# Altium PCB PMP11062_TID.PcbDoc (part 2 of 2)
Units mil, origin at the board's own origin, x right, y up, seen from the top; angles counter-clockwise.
Board outline 8000 x 4750 mil, 2 copper layers (Top Layer, Bottom Layer), stack 62 mil thick; 95 components, 41 nets, 236 pads, 20 vias.
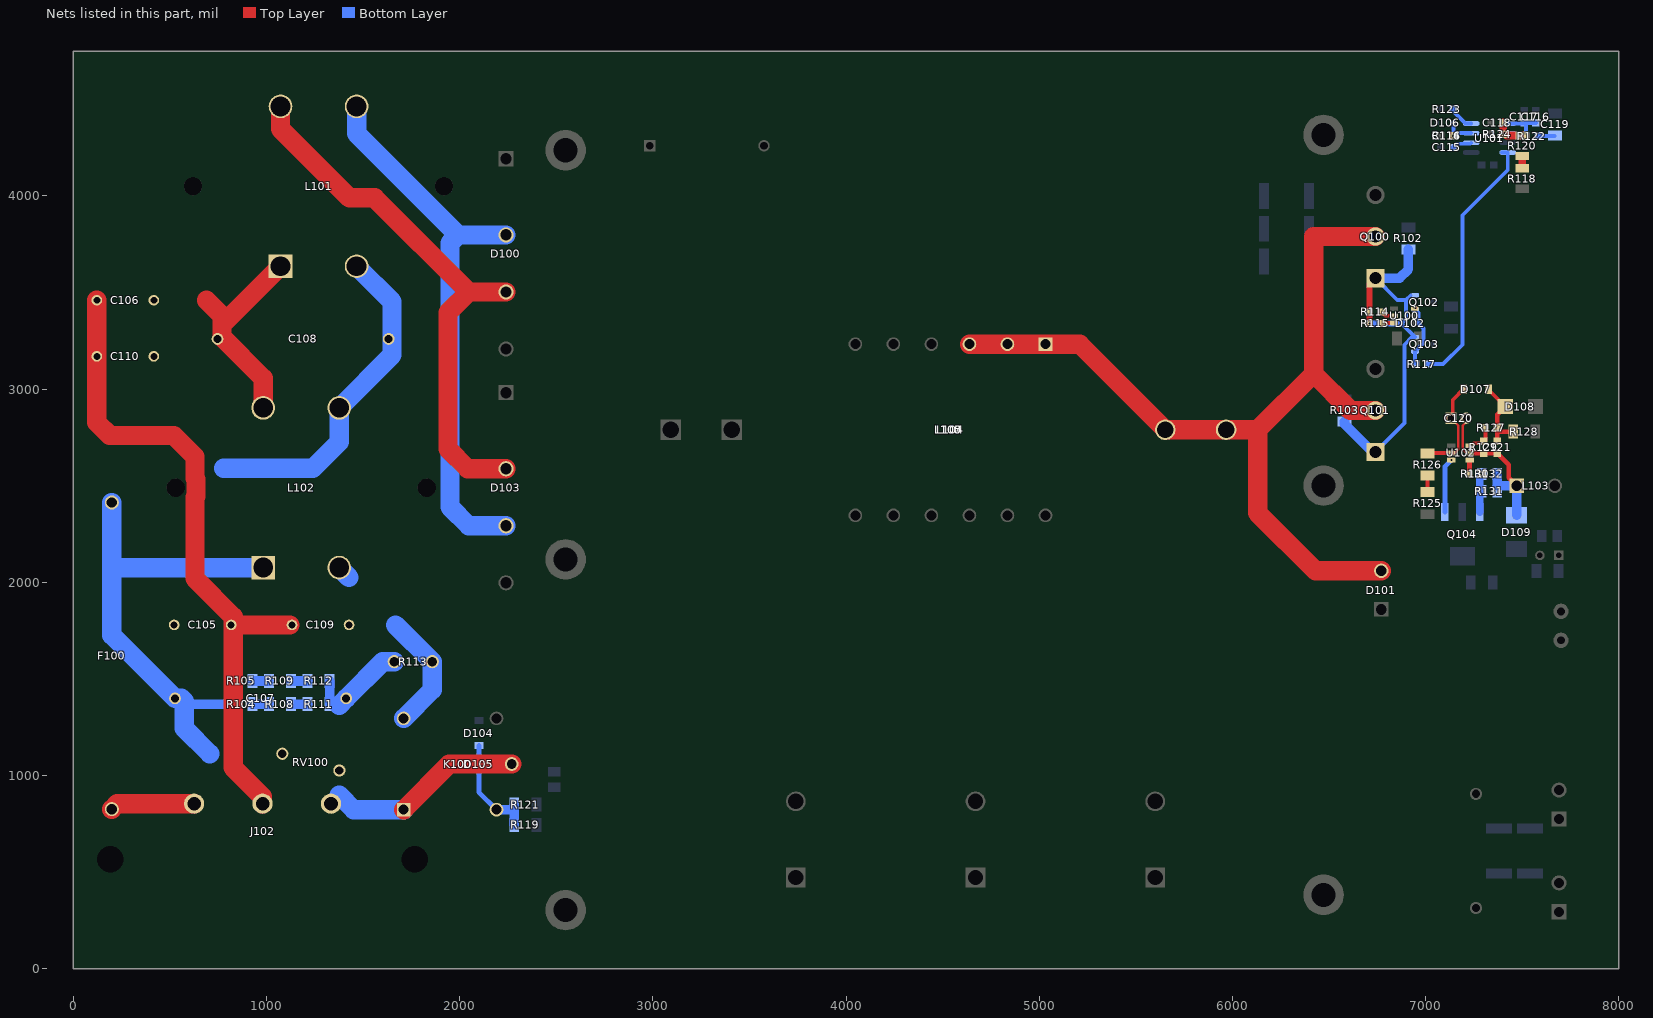
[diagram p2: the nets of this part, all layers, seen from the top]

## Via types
v1: diameter 28, hole 10, Top Layer to Bottom Layer, 20 vias

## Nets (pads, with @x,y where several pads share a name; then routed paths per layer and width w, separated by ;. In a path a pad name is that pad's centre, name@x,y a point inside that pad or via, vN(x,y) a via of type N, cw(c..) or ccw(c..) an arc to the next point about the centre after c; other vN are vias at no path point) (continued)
NetC105_1: C105.1 C107.1 F100.2 L102.1 R104.2 R105.2 RV100.2 | length 2642.2
  Bottom Layer w50: 590,1370 R104.2@812.91,1370 R105.2@812.91,1490
  Bottom Layer w100: F100.2@200,2413.7 200,1727.09 C107.1@527.09,1400 560,1400 575.51,1384.49 575.51,1244.49 706.69,1113.31 ; 213.39,2076.61 L102.1@983.15,2076.61
NetC106_1: C106.1 C108.1 L101.1 L102.4 | length 1106.8
  Top Layer w100: 690,3460 770,3380 770,3333.46 ; L102.4@983.15,2903.39 983.15,3056.85 770,3270 770,3333.46 ; L101.1@1073.15,3636.61 770,3333.46
NetC107_2: C107.2 J102.2 K100.1 K100.3 R111.1 R112.1 R113.2 RV100.1 | length 1517.9
  Top Layer w100: K100.1@1710.47,823.78 1946.69,1060 K100.3@2269.53,1060
  Bottom Layer w50: R111.1@1327.09,1370 R112.1@1327.09,1490
  Bottom Layer w100: 1377.64,898.31 1452.17,823.78 K100.1@1710.47,823.78 ; 1377.64,1364.72 C107.2@1412.91,1400 1602.91,1590 R113.2@1661.57,1590
NetC108_2: C108.2 C110.2 L101.2 L102.3 | length 1752.3
  Bottom Layer w100: 780,2590 1240,2590 1376.85,2726.85 L102.3@1376.85,2903.39 1650,3176.54 1650,3453.46 L101.2@1466.85,3636.61
NetC109_2: C109.2 K100.2 L102.2 R113.1 | length 695.6
  Bottom Layer w100: L102.2@1376.85,2076.61 1427.64,2025.83 ; 1668.43,1780 R113.1@1858.43,1590 1858.43,1444.17 K100.2@1710.47,1296.22
NetC114_1: C114.1 D106.1 R116.1 U101.3 | length 166.4
  Bottom Layer w20: v1(7141.5,4311.46) 7151.46,4311.46 7165,4325 U101.3@7235.51,4325 ; C114.1@7143.31,4313.27 D106.1@7143.31,4380
NetC115_1: C115.1 U101.2 | length 103.8
  Bottom Layer w20: C115.1@7141.5,4251.46 7160.04,4270 7230.51,4270 U101.2@7235.51,4275
NetC116_1: C116.1 C117.1 R122.2 U101.5 | length 219
  Bottom Layer w20: U101.5@7424.49,4375 7506.5,4375 C117.1@7510,4378.5 ; R122.2@7518.5,4310 7518.5,4370 C117.1@7510,4378.5 ; C116.1@7570,4378.5 C117.1@7510,4378.5
NetC118_1: C118.1 R120.1 R124.2 U101.6 | length 155.4
  Top Layer w39.37: C118.1@7401.5,4380 7401.5,4330.2 v1(7406.69,4325) 7418.54,4313.15 R120.1@7500,4313.15
NetC119_1: C119.1 R122.1 | length 85.6
  Bottom Layer w20: R122.1@7581.5,4310 C119.1@7667.09,4310
NetC120_1: C120.1 D107.1 R126.2 U102.2 | length 503.9
  Top Layer w12: C120.1@7130.63,2850 7168.28,2812.35 7168.28,2688.28 7150,2670 U102.2@7132.76,2670
  Top Layer w20: R126.2@7012.91,2670 U102.2@7132.76,2670 ; C120.1@7140,2859.37 7140,2944.47 D107.1@7195.53,3000
NetC120_2: C120.2 C121.2 D109.1 L103.1 R129.1 R131.2 R132.2 U102.5 | length 852.9
  Top Layer w12: C120.2@7209.37,2850 7209.37,2829.37 7191.72,2811.72 7191.72,2688.28 7210,2670 U102.5@7227.24,2670
  Top Layer w25: U102.5@7227.24,2670 R129.1@7301.57,2670 ; R129.1@7300,2668.5 C121.2@7370,2668.5 7430,2608.5 7430,2541.57 L103.1@7471.57,2500
  Bottom Layer w50: R131.2@7370,2500 R132.2@7370,2561.46 ; 7398.54,2500 L103.1@7471.57,2500 D109.1@7471.57,2348.58
NetC121_1: C121.1 D107.2 D108.1 R127.2 R128.2 | length 404.5
  Top Layer w20: D107.2@7324.47,3000 7324.47,2996.79 D108.1@7411.26,2910
  Top Layer w25: C121.1@7370,2731.5 7370,2780 ; D108.1@7411.26,2910 7370,2868.74 7370,2780 ; R128.2@7452.91,2780 7370,2780
NetD100_2: D100.2 D103.3 L101.3 | length 2886.5
  Bottom Layer w100: L101.3@1466.85,4463.39 1466.85,4323.15 1991.57,3798.43 ; D103.3@2240,2293.15 2046.85,2293.15 1950,2390 1950,3756.85 1991.57,3798.43 ; D100.2@2240,3798.43 1991.57,3798.43
NetD100_3: D100.3 D103.2 L101.4 | length 2832.3
  Top Layer w100: L101.4@1073.15,4463.39 1073.15,4346.85 1430,3990 1560,3990 2046.85,3503.15 ; D103.2@2240,2588.43 2041.57,2588.43 1940,2690 1940,3396.3 2046.85,3503.15 ; D100.3@2240,3503.15 2046.85,3503.15
NetD101_2: D101.2 L100.2 L104.1 L104.2 L104.3 L105.2 Q100.2 Q101.2 | length 4708.1
  Top Layer w100: L104.3@4638.43,3232.91 L104.2@4835.28,3232.91 L104.1@5032.13,3232.91 5209.13,3232.91 L100.2@5652.05,2790 6130,2790 ; Q101.2@6740,2890 6610,2890 6420,3080 ; Q100.2@6740,3790 6420,3790 6420,3080 ; D101.2@6770,2060 6430,2060 6130,2360 6130,2790 ; 6130,2790 6420,3080
NetD102_1: D102.1 Q100.1 Q101.1 Q102.2 Q103.2 R102.2 R103.2 R114.1 R115.2 | length 2038
  Top Layer w29.53: v1(6708.5,3340) R114.1@6708.5,3400 Q100.1@6708.5,3543.5
  Bottom Layer w20: Q101.1@6740,2675 6890,2825 6890,3230 6929.57,3269.57 Q103.2@6944.41,3269.57 6875.39,3338.59 D102.1@6875.39,3340.16 6898.7,3363.46 6898.7,3462.52 ; Q100.1@6740,3575 6852.48,3462.52 6898.7,3462.52 ; 6922.64,3486.46 6898.7,3462.52
  Bottom Layer w29.53: v1(6708.5,3340) D102.1@6875.24,3340
  Bottom Layer w50: R103.2@6580,2832.91 6580,2820 Q101.1@6725,2675 ; Q100.1@6740,3575 6865,3575 6910,3620 R102.2@6910,3722.91
NetD102_2: D102.2 Q102.1 Q103.1 R117.1 U100.6 | length 314.1
  Bottom Layer w20: R117.1@6944.41,3134.09 Q103.1@6944.41,3194.77 6988.7,3239.06 6988.7,3313.46 D102.2@6962.01,3340.16 6962.01,3394.53 Q102.1@6944.88,3411.65
  other v1: 6946.46,3419.51
NetD104_2: D104.2 D105.2 | length 52.2
  Bottom Layer w25: D105.2@2100,1103.31 D104.2@2100,1155.53
NetD105_1: D105.1 K100.4 R119.1 R121.1 | length 442.1
  Bottom Layer w25: D105.1@2100,1016.69 2100,914.57 K100.4@2190.79,823.78 ; R121.1@2262.91,830 R121.1@2282.91,850
  Bottom Layer w50: K100.4@2190.79,823.78 R121.1@2269.13,823.78 ; R119.1@2282.91,745.04 R121.1@2282.91,850
NetF100_1: F100.1 J102.1 | length 437.6
  Top Layer w100: F100.1@200,826.3 228.7,855 J102.1@625.67,855
NetQ104_1: Q104.1 U102.3 | length 282.2
  Bottom Layer w25: Q104.1@7099.45,2364.17 7099.45,2599.29 v1(7132.76,2632.6)
NetQ104_3: Q104.3 R130.1 R131.1 R132.1 | length 187.8
  Bottom Layer w39.37: Q104.3@7280.55,2364.17 R132.1@7280.55,2552.01
  other v1: 7287.5,2561.46
NetR104_1: R104.1 R108.2 | length 85.8
  Bottom Layer w50: R104.1@927.09,1370 R108.2@1012.91,1370
NetR105_1: R105.1 R109.2 | length 85.8
  Bottom Layer w50: R105.1@927.09,1490 R109.2@1012.91,1490
NetR108_1: R108.1 R111.2 | length 85.8
  Bottom Layer w50: R108.1@1127.09,1370 R111.2@1212.91,1370
NetR109_1: R109.1 R112.2 | length 85.8
  Bottom Layer w50: R109.1@1127.09,1490 R112.2@1212.91,1490
NetR114_2: R114.2 U100.2 | length 72.7
  Top Layer w20: R114.2@6771.5,3400 6791.5,3380 U100.2@6835.87,3380
NetR115_1: R115.1 U100.3 | length 61.8
  Top Layer w20: R115.1@6774.09,3342.6 U100.3@6835.87,3342.6
NetR117_2: R117.2 U101.8 | length 1341.5
  Bottom Layer w20: R117.2@7011.5,3130 7090,3130 7190,3230 7190,3900 7424.49,4134.49 U101.8@7424.49,4225 U101.8@7395,4225
NetR118_1: R118.1 R120.2 | length 63.7
  Top Layer w39.37: R118.1@7500,4143.15 R120.2@7500,4206.85
NetR123_2: R123.2 U101.4 | length 130.9
  Bottom Layer w20: R123.2@7141.5,4450 7141.5,4440 7206.5,4375 U101.4@7235.51,4375
NetR125_2: R125.2 R126.1 | length 85.8
  Top Layer w20: R125.2@7010,2467.09 R126.1@7010,2552.91
NetR127_1: R127.1 R129.2 U102.6 | length 154.8
  Top Layer w20: U102.6@7227.24,2707.4 7237.4,2707.4 7250,2720 7288.5,2720 R129.2@7300,2731.5 7308.5,2740 R127.1@7308.5,2800
NetR130_2: R130.2 U102.4 | length 68.4
  Top Layer w25: R130.2@7227.24,2564.2 U102.4@7227.24,2632.6
PE: C105.2 C106.2 C109.1 C110.1 J102.3 | length 3452.8
  Top Layer w100: C106.2@122.36,3460 C110.1@122.36,3170 122.36,2827.64 190,2760 520,2760 630,2650 630,2539.05 635.51,2533.54 635.51,2446.46 630,2440.95 630,2020 827.64,1822.36 C105.2@827.64,1780 ; J102.3@980,855 980,890 827.64,1042.36 C105.2@827.64,1780 ; C109.1@1122.36,1780 C105.2@827.64,1780
pads on no net: J102.MH1 J102.MH2 L101.MH1 L101.MH2 L102.MH1 L102.MH2 L104.7 L104.8 L104.9 L104.10 L104.11 L104.12 U102.1

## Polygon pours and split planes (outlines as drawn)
NetC103_2 on Top Layer "C103_2" (solid, remove dead copper, pour order 54): 2850,2000 2850,1900 2850,440 2850,200 2850,30 2830,10 2810,10 2210,10 2190,30 2190,450 2190,1300 2250,1360 2370,1360 2380,1360 2400,1380 2400,1400 2400,1740 2180,1960 2180,2030 2200,2050 2280,2050 2430,2200 2430,2500 2430,4660 2450,4680 2480,4680 3600,4680 3620,4660 3620,4630 3620,4490 3620,3140 3040,2560 2870,2390 2850,2390
GND on Top Layer "GND" (solid, remove dead copper, pour order 56): 2210,10 2190,30 2190,80 2190,410 2190,1300 2240,1350 2250,1360 3690,1360 5360,1360 5610,1360 5930,1680 5930,2260 5930,4660 5950,4680 5990,4680 7970,4680 7990,4660 7990,4650 7990,30 7970,10
B+ on Top Layer "B+" (solid, remove dead copper, pour order 53): 6810,1910 6830,1890 6830,1730 6830,1610 7340,1100 7640,1100 7720,1100 7740,1080 7740,1060 7740,690 7720,670 7710,670 6460,670 6160,370 5910,120 3720,120 3650,120 3630,140 3630,170 3630,560 3650,580 3660,580 5640,580 6350,1290 6350,1780 6350,1890 6370,1910
NetD101_2 on Top Layer "D101_2" (solid, remove dead copper, pour order 51): 4580,3160 4600,3140 5210,3140 5300,3050 6350,2000 6770,2000 6810,2000 6830,2020 6830,2050 6830,2130 6810,2150 6790,2150 6630,2150 6340,2440 6340,2450 6340,2560 6590,2810 6620,2840 6680,2840 6780,2840 6800,2860 6800,2870 6800,2930 6780,2950 6760,2950 6690,2950 6610,3030 6610,3060 6610,3670 6680,3740 6770,3740 6780,3740 6800,3760 6800,3820 6780,3840 6431.57,3840 6350,3840 6330,3820 6330,3790 6330,3510 6220,3400 6090,3400 4600,3400 4580,3380
NetC103_1 on Top Layer "C103_1" (solid, remove dead copper, pour order 50): 2210,4250 2190,4230 2190,4210 2190,4160 2200,4150 2210,4140 2218.35,4140 2220,4140 2240,4120 2450,3910 2450,3740 2450,3150 2340,3040 2300,3040 2210,3040 2190,3020 2190,3010 2190,2930 2270,2850 2310,2850 2470,2850 2650,2670 3230,2670 4010,2670 4500,3160 4500,3190 4500,3290 4480,3310 4420,3310 4410,3320 4290,3440 3920,3810 3550,3810 3130,4230 3130,4290 3110,4310 3050,4310 2270,4310
NetD100_3 on Top Layer "D100_3" (solid, remove dead copper, pour order 48): 2270,2540 2290,2560 2290,2620 2290,2650 2270,2670 2250,2670 2200,2670 2000,2870 2000,3200 2000,3310 2140,3450 2270,3450 2290,3470 2290,3540 2270,3560 2218.35,3560 2160,3560 1990,3730 1990,3770 1990,4000 1800,4190 1430,4190 1340,4190 1160,4370 1160,4410 1160,4520 1140,4540 1110,4540 970,4540 950,4520 950,4480 950,4200 1270,3880 1520,3880 1580,3880 1690,3770 1730,3730 1730,3640 1730,3500 1830,3400 1830,3140 1730,3040 1730,2600 1790,2540
NetF100_1 on Top Layer "F100_1" (solid, remove dead copper, pour order 40): 50,940 30,920 30,850 30,720 50,700 100,700 660,700 680,720 680,800 680,920 660,940
NetC107_2 on Top Layer "C107_2" (solid, remove dead copper, pour order 43): 1710,1620 1690,1640 1670,1640 1550,1640 1400,1640 1310,1550 1310,1510 1310,1330 1340,1300 1340,1210 1340,940 1290,890 1280,880 1280,860 1280,720 1300,700 1330,700 1740,700 1760,720 1760,760 1760,1150 1640,1270 1640,1290 1640,1410 1710,1480
NetC106_1 on Top Layer "C106_1" (solid, remove dead copper, pour order 47): 390,3450 390,3440 410,3420 430,3420 550,3420 730,3240 730,3150 730,3060 930,2860 950,2840 1020,2840 1060,2840 1080,2860 1090,2870 1090,3060 1090,3160 1150,3220 1150,3560 1150,3690 1130,3710 1020,3710 580,3710 390,3520
GND on Bottom Layer "GND" (solid, remove dead copper, pour order 55): 2210,10 2190,30 2190,80 2190,410 2190,1300 2240,1350 2250,1360 3690,1360 5360,1360 5610,1360 5930,1680 5930,2260 5930,4660 5950,4680 5990,4680 7970,4680 7990,4660 7990,4650 7990,30 7970,10
NetC103_2 on Bottom Layer "C103_2" (solid, remove dead copper, pour order 52): 2200,2050 2180,2030 2180,2010 2180,1960 2200,1940 2240,1940 2830,1940 2850,1960 2850,1980 2850,3030 3350,3530 3530,3530 6210,3530 6230,3550 6230,3570 6230,4040 5590,4680 5420,4680 2450,4680 2430,4660 2430,4630 2430,4500 2430,3920 2430,3440 2260,3270 2250,3260 2220,3260 2210,3260 2190,3240 2190,3170 2200,3160 2218.35,3160 2317.52,3160 2430,3047.52 2430,2200 2280,2050
NetD100_2 on Bottom Layer "D100_2" (solid, remove dead copper, pour order 49): 1390,4520 1410,4540 1490,4540 1530,4540 1850,4220 2170,3900 2230,3900 2270,3900 2290,3880 2290,3850 2290,3770 2270,3750 2218.35,3750 2218.35,3748.35 2210,3740 2050,3580 2050,3480 2050,3370 2050,3050 2050,2500 2190,2360 2280,2360 2300,2340 2300,2310 2300,2260 2280,2240 2260,2240 1950,2240 1730,2460 1730,3400 1730,3580 1630,3680 1390,3920 1390,4270
NetF100_1 on Bottom Layer "F100_1" (solid, remove dead copper, pour order 39): 50,940 30,920 30,850 30,720 50,700 100,700 660,700 680,720 680,800 680,920 660,940
NetC105_1 on Bottom Layer "C105_1" (solid, remove dead copper, pour order 41): 1110,1060 1130,1080 1130,1110 1130,1140 1100,1170 1070,1170 960,1170 830,1300 827.64,1302.36 827.64,1310 827.64,1382.36 550,1660 550,1710 550,1930 640,2020 750,2020 1030,2020 1030,2130 1030,2150 1000,2180 860,2180 580,2180 290,2470 170,2470 120,2470 100,2450 100,2430 100,1080 120,1060
NetC107_2 on Bottom Layer "C107_2" (solid, remove dead copper, pour order 42): 1710,1620 1690,1640 1670,1640 1550,1640 1400,1640 1310,1550 1310,1510 1310,1330 1340,1300 1340,1210 1340,940 1290,890 1280,880 1280,860 1280,720 1300,700 1330,700 1740,700 1760,720 1760,760 1760,1150 1640,1270 1640,1290 1640,1410 1710,1480
NetC109_2 on Bottom Layer "C109_2" (solid, remove dead copper, pour order 44): 1310,2160 1330,2180 1370,2180 1550,2180 1677,2180 2037,1820 2037,1670 2037,1547 1730,1240 1700,1240 1690,1240 1660,1270 1660,1300 1660,1400 1730,1470 1730,1600 1730,1630 1700,1660 1420,1660 1400,1680 1400,1700 1400,1960 1310,2050
NetC108_2 on Bottom Layer "C108_2" (solid, remove dead copper, pour order 45): 410,3200 400,3200 390,3190 390,3180 390,3150 390,3040 390,2680 520,2550 670,2400 790,2400 1530,2400 1700,2570 1700,2700 1700,3560 1550,3710 1440,3710 1410,3710 1390,3690 1390,3670 1390,3160 1310,3080 1310,3000 1310,2820 1140,2650 850,2650 580,2920 510,2990 510,3140 510,3180 490,3200
NetC106_1 on Bottom Layer "C106_1" (solid, remove dead copper, pour order 46): 390,3450 390,3440 410,3420 430,3420 550,3420 730,3240 730,3150 730,3060 930,2860 950,2840 1020,2840 1060,2840 1080,2860 1090,2870 1090,3060 1090,3160 1150,3220 1150,3560 1150,3690 1130,3710 1020,3710 580,3710 390,3520

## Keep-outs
Keep-Out Layer:
  text ".Layer_Name" at 577,-858.49 h60

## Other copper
Top Layer:
  text ".Layer_Name" at 577,-858.49 h60
Bottom Layer:
  text ".Layer_Name" at 577,-858.49 h60

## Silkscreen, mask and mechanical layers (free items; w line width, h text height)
Top Overlay:
  lines w7.01: 0,3543.31 0,0 6692.91,0
  lines w10: 6740,3440 6760,3460 6870,3460 6890,3480 6900,3480 ; 7230,2310 7230,2510 ; 7030,1960 7030,2200 7140,2310 7300,2310 7310,2300 7310,1990 7250,1930 7060,1930 7030,1960
  text ".PRJ_Number" at 5480,50 h60
  text ".PCB_Rev" at 6080,50 h60
  text ".Layer_Name" at 577,-858.49 h60
Bottom Overlay:
  text ".Layer_Name" at 577,-858.49 h60
Top Paste:
  text ".Layer_Name" at 577,-858.49 h60
Bottom Paste:
  text ".Layer_Name" at 577,-858.49 h60
Top Solder:
  text ".Layer_Name" at 577,-858.49 h60
  text ".Layer_Name" at 577,-858.49 h60
Bottom Solder:
  text ".Layer_Name" at 577,-858.49 h60
Drill Guide:
  text ".Layer_Name" at 577,-858.49 h60
M1 Board Outline:
  the board outline again, w7
  text ".Layer_Name" at 577,-858.49 h60
M2 Board Dimensions:
  rectangle: 125,-400 500,-275
  rectangle: 0,-275 125,-150
  lines w7: 0,-275 1000,-275 ; 125,-400 125,-150 ; 250,-400 250,-150 ; 500,-400 500,-150 ; 750,-400 750,-150 ; 0,-400 0,-150 1000,-150 1000,-400 0,-400
  text ".Layer_Name" at 577,-858.49 h60
M3 3D STEP Top:
  text ".Layer_Name" at 577,-858.49 h60
M4 3D STEP Bottom:
  text ".Layer_Name" at 577,-858.49 h60
M5 Assembly Top:
  lines w10: -292,-930.17 6308,-930.17 ; -292,-726.83 6310,-726.83 ; -292,-523.5 -292,-1133.5 3713,-1133.5 6310,-1133.5 6310,-523.5 -291.5,-523.5 -291.5,-1133.5 1284,-1133.5 ; 2173,-1133.5 2173,-523.5 ; 3440,-726.83 3440,-523.5 ; 4280,-726.83 4280,-523.5 ; 4902,-1140 4902,-937.17
  text "COMPONENTS MARKED 'DNP' SHOULD NOT BE POPULATED." at 1153.5,-318.5 h60
  text "ASSEMBLY VARIANT:" at 1153,-434 h60
  text ".VariantName" at 2189,-434 h60
  text "PCB VIEWED FROM TOP SIDE" at -228.5,-655.67 h60
  text "BOARD #:" at 2248,-655.67 h60
  text ".PRJ_Number" at 2793.5,-655.67 h60
  text "REV:" at 3638,-655.67 h60
  text ".PCB_Rev" at 3929.5,-655.67 h60
  text "SVN REV:" at 4476,-655.67 h60
  text ".VersionControl_RevNumber" at 4982,-655.67 h60
  text "PLOT NAME =" at -228.5,-1064.34 h60
  text ".plot_File_Name" at 577,-1064.34 h60
  text "GENERATED    :" at 2250,-1064.34 h60
  text ".Print_Date" at 3119.5,-1064.34 h60
  text ".Print_Time" at 3848.5,-1064.34 h60
  text "TEXAS INSTRUMENTS" at 5113,-1064.34 h60
M6 Assembly Bottom:
  lines w10: -292.5,-727.33 6309.5,-727.33 ; -290.5,-930.67 6309.5,-930.67 ; 1115.5,-1140.5 1115.5,-937.67 ; 1737.5,-727.33 1737.5,-524 ; 2577.5,-727.33 2577.5,-524 ; 3844.5,-1134 3844.5,-524 ; 4733.5,-1134 6309,-1134 6309,-524 -292.5,-524 -292.5,-1134 2304.5,-1134 6309.5,-1134 6309.5,-524
  text "COMPONENTS MARKED 'DNP' SHOULD NOT BE POPULATED." at 6102,-318 h60
  text ".VariantName" at 5058,-434 h60
  text "ASSEMBLY VARIANT:" at 6097,-434 h60
  text ".VersionControl_RevNumber" at 1035.5,-656.17 h60
  text "SVN REV:" at 1541.5,-656.17 h60
  text ".PCB_Rev" at 2088,-656.17 h60
  text "REV:" at 2379.5,-656.17 h60
  text ".PRJ_Number" at 3224,-656.17 h60
  text "BOARD #:" at 3769.5,-656.17 h60
  text "PCB VIEWED FROM BOTTOM SIDE" at 6246,-656.17 h60
  text "TEXAS INSTRUMENTS" at 904.5,-1064.84 h60
  text ".Print_Time" at 2169,-1064.84 h60
  text ".Print_Date" at 2898,-1064.84 h60
  text "GENERATED    :" at 3767.5,-1064.84 h60
  text ".plot_File_Name" at 5440.5,-1064.84 h60
  text "PLOT NAME =" at 6246,-1064.84 h60
M9 Title Sheet:
  drawing of 57 lines, arcs and shapes, not listed
  text "1" at 739.84,8036.5 h70
  text "2" at 3235.5,8036.5 h70
  text "3" at 5724.84,8036.5 h70
  text "4" at 8231.51,8036.5 h70
  text "5" at 10730.5,8036.5 h70
  text "6" at 13235.5,8036.5 h70
  text "A" at -416.5,6893.5 h70
  text "A" at 14383.5,6893.5 h70
  text "B" at -416.5,4513.5 h70
  text "B" at 14383.5,4513.5 h70
  text "C" at -416.5,2138.5 h70
  text "C" at 14383.5,2138.5 h70
  text "PROJECT TITLE:" at 11343.5,277.5 h45
  text ".PRJ_Title" at 11393.5,144.17 h70
  text "DESIGNED FOR:" at 11343.5,-23.5 h45
  text ".PRJ_Customer" at 11393.5,-163.5 h70
  text "D" at -416.5,-231.5 h70
  text "D" at 14383.5,-231.5 h70
  text "FILE NAME:" at 11343.5,-323.5 h45
  text ".PCB_File_Name_No_Path" at 11393.5,-443.5 h70
  text "Texas Instruments (TI) and/or its licensors do not warrant the accuracy or completeness of this specification" at 6374,-605.34 h45
  text "ENGINEER:" at 11343.5,-613.5 h45
  text "LAYOUT BY:" at 12848.5,-613.5 h45
  text "or any information contained therein. TI and/or its licensors do not warrant that this design will meet" at 6329.01,-718 h45
  text ".PRJ_Engineer" at 11393.5,-768.49 h70
  text ".PCB_Layout" at 12899,-768.49 h70
  text "the specifications, will be suitable for your application or fit for any particular purpose, or will operate in" at 6329.01,-830.67 h45
  text ".Layer_Name" at 577,-858.49 h60
  text "ALTIUM DESIGNER VERSION:" at 12848.5,-923.5 h45
  text "an implementation. TI and/or its licensors do not warrant that the design is production worthy. You should" at 6329.01,-943.33 h45
  text "completely validate and test your design implementation to confirm the system functionality for your application." at 6374,-1056 h45
  text ".print_Scale" at 11393.5,-1056.83 h70
  text ".Application_BuildNumber" at 12899,-1056.83 h70
  text "1" at 739.84,-1263.5 h70
  text "2" at 3235.5,-1263.5 h70
  text "3" at 5724.84,-1263.5 h70
  text "4" at 8231.51,-1263.5 h70
  text "5" at 10730.5,-1263.5 h70
  text "6" at 13235.5,-1263.5 h70
M10 Fab Notes:
  drawing of 185 lines, arcs and shapes, not listed
  text "DESIGN INFORMATION" at 12381.02,5910 h60
  text "MIN. TRACK WIDTH:" at 11736.46,5730 h60
  text "10" at 12832.7,5730 h60
  text "MIL" at 12987.46,5730 h60
  text "MIN. CLEARANCE:" at 11736.46,5598 h60
  text "0.2" at 12772.7,5598 h60
  text "mm" at 12987.46,5598 h60
  text "MIN. VIA PAD SIZE:" at 11736.46,5466 h60
  text "10" at 12802.71,5466 h60
  text "MIL" at 12987.46,5466 h60
  text "0.05mm (2MIL)" at 12431.46,5324.29 h60
  text "MINIMUM ANNULAR RING" at 11407.23,5320 h60
  text "EXTERNAL" at 13139.46,5320 h60
  text "PER" at 11607.23,5202 h60
  text "IPC-D-275 CLASS 2 LEVEL C" at 11827.23,5202 h60
  text "MIL, HOLES" at 13315.46,5089.71 h60
  text "+/-" at 12923,5089 h60
  text "+/-" at 13777,5089 h60
  text "REGISTRATION TOLERANCES:" at 11407.23,5084 h60
  text "METAL" at 12607,5084 h60
  text "5" at 13183.2,5084 h60
  text "3" at 14016.2,5084 h60
  text "MIL" at 14132.46,5084 h60
  text "MATERIAL:" at 11332.46,4874.54 h60
  text "FR-4 High Tg" at 12318.9,4734.21 h60
  text "FR-408" at 11753.46,4725.64 h60
  text "X" at 12165.46,4725.64 h60
  text "OTHER" at 13241.46,4725.64 h60
  text "62 MIL (1.6mm) +/-10%" at 12073.56,4562.92 h60
  text "THICKNESS:" at 11407.23,4558.64 h60
  text "X" at 11945.4,4558.64 h60
  text "OTHER" at 13358.46,4558.64 h60
  text "TOLERANCE:" at 11407.23,4400.64 h60
  text "X" at 12246.53,4400.64 h60
  text "ANSI IPC-6012 TYPE 3 CLASS 2" at 12433.48,4400.64 h60
  text "OTHER +/-" at 12433.46,4244.64 h60
  text "BOW & TWIST:" at 11407.23,4087.64 h60
  text "X" at 12246.53,4087.64 h60
  text "ANSI IPC-6012 TYPE 3 CLASS 2" at 12433.48,4087.64 h60
  text "OTHER +/-" at 12433.46,3929.13 h60
  text "DRILLING:" at 11332.46,3790.64 h60
  text "REFERENCE:" at 11407.23,3673.64 h60
  text "X" at 12055.46,3673.64 h60
  text "AS SHOWN" at 12242.46,3673.64 h60
  text "X" at 12956.46,3673.64 h60
  text "NC_DRILL FILES" at 13093.46,3673.64 h60
  text "PTH MIN COPPER THICKNESS:" at 11407.23,3515.64 h60
  text "X" at 12757.46,3515.64 h60
  text "1MIL" at 12894.46,3515.64 h60
  text "OTHER" at 13391.46,3515.64 h60
  text "BOARD FINISH:" at 11332.46,3356.64 h60
  text "SILKSCREEN:" at 11487.68,3238.64 h60
  text "X" at 12436.46,3238.64 h60
  text "TOP" at 12562.46,3238.64 h60
  text "X" at 12946.46,3238.64 h60
  text "BOTTOM" at 13073.46,3238.64 h60
  text "SILKSCREEN COLOR:" at 11487.68,3071.64 h60
  text "X" at 12435.42,3071.64 h60
  text "WHITE" at 12562.46,3071.64 h60
  text "OTHER" at 13073.46,3071.64 h60
  text "SOLDER RESIST COLOR:" at 11487.68,2901.64 h60
  text "X" at 12055.42,2742.44 h60
  text "GREEN" at 12182.46,2742.44 h60
  text "BLUE" at 12773.46,2742.44 h60
  text "OTHER" at 13311.46,2742.44 h60
  text "IMMERSION GOLD (ENIG)" at 12393.46,2553.92 h60
  text "ENEPIG" at 13731,2550.64 h60
  text "SURFACE FINISH:" at 11332.46,2549.64 h60
  text "IMM. TIN/SILVER OR EQUIV" at 11662,2392.64 h60
  text "OTHER" at 13093.46,2392.64 h60
  text "X" at 11500,2390 h60
  text "ARRAY/PANEL:" at 11332.46,2213.64 h60
  text "CUT AND TRIM PER MECH LAYER 1" at 12393.46,2209.35 h60
  text "N.C. ROUTE" at 12393.46,2057.64 h60
  text "X" at 13072.46,2057.64 h60
  text "V. SCORE" at 13259.46,2057.64 h60
  text "CERTIFICATION:" at 11332.46,1920.64 h60
  text "MATERIALS AND WORKMANSHIP FOR ALL PCBS" at 12057.46,1920.64 h60
  text "TO MEET OR EXCEED THE REQUIREMENTS OF:" at 12057.46,1822.64 h60
  text "X" at 11683.96,1686.13 h60
  text "ANSI IPC-A-600F CLASS ->" at 11822.96,1686.13 h60
  text "X" at 13462.02,1686.13 h60
  text "2" at 13580.96,1686.14 h60
  text "1" at 13265.96,1684.64 h60
  text "3" at 13934.96,1684.64 h60
  text "X" at 11686.02,1526.64 h60
  text "UL 94V-0" at 11822.96,1526.64 h60
  text "X" at 12498.02,1526.64 h60
  text "RoHS" at 12634.96,1526.64 h60
  text "OTHER" at 13279.36,1526.64 h60
  text "PER ORDER" at 13676.42,1526.64 h60
  text "ADDITIONAL REQUIREMENTS:" at 11332.46,1385.64 h60
  text "MICROSECTION:" at 11407.23,1270.64 h60
  text "YES" at 12312.96,1270.64 h60
  text "REQUIRED" at 13174.46,1114.49 h60
  text "BARE BOARD ELEC. TEST:" at 11407.23,1111.64 h60
  text "NONE" at 12712.96,1111.64 h60
  text "PER ORDER" at 13766.46,1111.64 h60
  text "X" at 12590,1110 h60
  text "MANUFACTURER'S UL:" at 11407.23,954.64 h60
  text "RAIL" at 12572.96,950.35 h60
  text "METAL" at 13064.77,950.35 h60
  text "X" at 13440,950 h60
  text "SILK" at 13576.46,950.35 h60
  text ".Layer_Name" at 577,-858.49 h60
M11 Gerber Information:
  lines w10: -292,-930.17 6308,-930.17 ; -292,-726.83 6310,-726.83 ; -292,-523.5 -292,-1133.5 3713,-1133.5 6310,-1133.5 6310,-523.5 -291.5,-523.5 -291.5,-1133.5 1284,-1133.5 ; 2173,-1133.5 2173,-523.5 ; 3440,-726.83 3440,-523.5 ; 4280,-726.83 4280,-523.5 ; 4902,-1140 4902,-937.17
  text "ALL ARTWORK VIEWED FROM TOP SIDE" at -228.5,-655.67 h60
  text "BOARD #:" at 2248,-655.67 h60
  text ".PRJ_Number" at 2793.5,-655.67 h60
  text "REV:" at 3638,-655.67 h60
  text ".PCB_Rev" at 3929.5,-655.67 h60
  text "SVN REV:" at 4476,-655.67 h60
  text ".VersionControl_RevNumber" at 4982,-655.67 h60
  text "LAYER NAME =" at -228.5,-858.49 h60
  text "PLOT NAME =" at -228.5,-1064.34 h60
  text ".plot_File_Name" at 577,-1064.34 h60
  text "GENERATED    :" at 2250,-1064.34 h60
  text ".Print_Date" at 3119.5,-1064.34 h60
  text ".Print_Time" at 3848.5,-1064.34 h60
  text "TEXAS INSTRUMENTS" at 5113,-1064.34 h60
M12 Stackup:
  drawing of 191 lines, arcs and shapes, not listed
  text "Layer" at 9790.58,7830 h60
  text "Name" at 10200.49,7830 h60
  text "Material" at 11130.23,7830 h60
  text "Thickness" at 11990,7830 h60
  text "Constant" at 12639.84,7830 h60
  text "Board Layer Stack" at 13209.7,7830 h60
  text "1" at 9790.58,7710 h60
  text "Top Overlay" at 10200.49,7710 h60
  text "2" at 9790.58,7590 h60
  text "Top Solder" at 10200.49,7590 h60
  text "Solder Resist" at 11130.23,7590 h60
  text "0.40mil" at 11990,7590 h60
  text "3.5" at 12639.84,7590 h60
  text "3" at 9790.58,7470 h60
  text "Top Layer" at 10200.49,7470 h60
  text "Copper" at 11130.23,7470 h60
  text "1.40mil" at 11990,7470 h60
  text "4" at 9790.58,7350 h60
  text "Dielectric1" at 10200.49,7350 h60
  text "FR-4" at 11130.23,7350 h60
  text "59.20mil" at 11990,7350 h60
  text "4.8" at 12639.84,7350 h60
  text "5" at 9790.58,7230 h60
  text "Bottom Layer" at 10200.49,7230 h60
  text "Copper" at 11130.23,7230 h60
  text "1.40mil" at 11990,7230 h60
  text "6" at 9790.58,7110 h60
  text "Bottom Solder" at 10200.49,7110 h60
  text "Solder Resist" at 11130.23,7110 h60
  text "0.40mil" at 11990,7110 h60
  text "3.5" at 12639.84,7110 h60
  text "7" at 9790.58,6990 h60
  text "Bottom Overlay" at 10200.49,6990 h60
  text ".Layer_Name" at 577,-858.49 h60
M13 Component Bodies Top:
  text ".Layer_Name" at 577,-858.49 h60
M14 Component Bodies Bottom:
  text ".Layer_Name" at 577,-858.49 h60
M15 Courtyards Top:
  text ".Layer_Name" at 577,-858.49 h60
M16 Courtyards Bottom:
  text ".Layer_Name" at 577,-858.49 h60
Drill Drawing:
  drawing of 170 lines, arcs and shapes, not listed
  text "Symbol" at 8269.68,3525.38 h72
  text "Quantity" at 8595.51,3525.38 h72
  text "Finished Hole Size" at 8952.62,3525.38 h72
  text "Plated" at 9614.62,3525.38 h72
  text "Hole Type" at 9898.98,3525.38 h72
  text "I" at 8260.35,3388.38 h49.82
  text "4" at 8595.51,3375.92 h60
  text "94.49mil (2.400mm)" at 8952.62,3375.92 h60
  text "NPTH" at 9614.62,3375.92 h60
  text "Round" at 9898.98,3375.92 h60
  text "E" at 8260.35,3238.92 h49.82
  text "2" at 8595.51,3226.46 h60
  text "137.80mil (3.500mm)" at 8952.62,3226.46 h60
  text "NPTH" at 9614.62,3226.46 h60
  text "Round" at 9898.98,3226.46 h60
  text "J" at 8260.35,3089.46 h49.82
  text "20" at 8595.51,3077 h60
  text "10.00mil (0.254mm)" at 8952.62,3077 h60
  text "PTH" at 9614.62,3077 h60
  text "Round" at 9898.98,3077 h60
  text "2" at 8595.51,2927.54 h60
  text "29.53mil (0.750mm)" at 8952.62,2927.54 h60
  text "PTH" at 9614.62,2927.54 h60
  text "Round" at 9898.98,2927.54 h60
  text "2" at 8595.51,2778.09 h60
  text "33.46mil (0.850mm)" at 8952.62,2778.09 h60
  text "PTH" at 9614.62,2778.09 h60
  text "Round" at 9898.98,2778.09 h60
  text "8" at 8595.51,2628.63 h60
  text "35.43mil (0.900mm)" at 8952.62,2628.63 h60
  text "PTH" at 9614.62,2628.63 h60
  text "Round" at 9898.98,2628.63 h60
  text "2" at 8595.51,2479.17 h60
  text "39.37mil (1.000mm)" at 8952.62,2479.17 h60
  text "PTH" at 9614.62,2479.17 h60
  text "Round" at 9898.98,2479.17 h60
  text "2" at 8595.51,2329.71 h60
  text "40.00mil (1.016mm)" at 8952.62,2329.71 h60
  text "PTH" at 9614.62,2329.71 h60
  text "Round" at 9898.98,2329.71 h60
  text "4" at 8595.51,2180.25 h60
  text "41.34mil (1.050mm)" at 8952.62,2180.25 h60
  text "PTH" at 9614.62,2180.25 h60
  text "Round" at 9898.98,2180.25 h60
  text "4" at 8595.51,2030.79 h60
  text "43.31mil (1.100mm)" at 8952.62,2030.79 h60
  text "PTH" at 9614.62,2030.79 h60
  text "Round" at 9898.98,2030.79 h60
  text "2" at 8595.51,1881.33 h60
  text "49.21mil (1.250mm)" at 8952.62,1881.33 h60
  text "PTH" at 9614.62,1881.33 h60
  text "Round" at 9898.98,1881.33 h60
  text "21" at 8595.51,1731.87 h60
  text "51.18mil (1.300mm)" at 8952.62,1731.87 h60
  text "PTH" at 9614.62,1731.87 h60
  text "Round" at 9898.98,1731.87 h60
  text "2" at 8595.51,1582.42 h60
  text "53.15mil (1.350mm)" at 8952.62,1582.42 h60
  text "PTH" at 9614.62,1582.42 h60
  text "Round" at 9898.98,1582.42 h60
  text "2" at 8595.51,1432.96 h60
  text "53.94mil (1.370mm)" at 8952.62,1432.96 h60
  text "PTH" at 9614.62,1432.96 h60
  text "Round" at 9898.98,1432.96 h60
  text "2" at 8595.51,1283.5 h60
  text "55.12mil (1.400mm)" at 8952.62,1283.5 h60
  text "PTH" at 9614.62,1283.5 h60
  text "Round" at 9898.98,1283.5 h60
  text "8" at 8595.51,1134.04 h60
  text "59.06mil (1.500mm)" at 8952.62,1134.04 h60
  text "PTH" at 9614.62,1134.04 h60
  text "Round" at 9898.98,1134.04 h60
  text "A" at 8260.35,997.04 h49.82
  text "6" at 8595.51,984.58 h60
  text "62.00mil (1.575mm)" at 8952.62,984.58 h60
  text "PTH" at 9614.62,984.58 h60
  text "Round" at 9898.98,984.58 h60
  text "B" at 8260.35,847.58 h49.82
  text "3" at 8595.51,835.12 h60
  text "70.00mil (1.778mm)" at 8952.62,835.12 h60
  text "PTH" at 9614.62,835.12 h60
  text "Round" at 9898.98,835.12 h60
  text "6" at 8595.51,685.66 h60
  text "78.74mil (2.000mm)" at 8952.62,685.66 h60
  text "PTH" at 9614.62,685.66 h60
  text "Round" at 9898.98,685.66 h60
  text "K" at 8260.35,548.66 h49.82
  text "4" at 8595.51,536.2 h60
  text "86.61mil (2.200mm)" at 8952.62,536.2 h60
  text "PTH" at 9614.62,536.2 h60
  text "Round" at 9898.98,536.2 h60
  text "D" at 8260.35,399.2 h49.82
  text "8" at 8595.51,386.75 h60
  text "102.36mil (2.600mm)" at 8952.62,386.75 h60
  text "PTH" at 9614.62,386.75 h60
  text "Round" at 9898.98,386.75 h60
  text "H" at 8260.35,249.74 h49.82
  text "6" at 8595.51,237.29 h60
  text "125.00mil (3.175mm)" at 8952.62,237.29 h60
  text "PTH" at 9614.62,237.29 h60
  text "Round" at 9898.98,237.29 h60
  text "120 Total" at 8595.51,87.83 h60
  text ".Layer_Name" at 577,-858.49 h60

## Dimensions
0,0 to 8000,0 on M2 Board Dimensions
0,0 to 0,4750 on M2 Board Dimensions
0,-400 to 1000,-400 on M2 Board Dimensions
